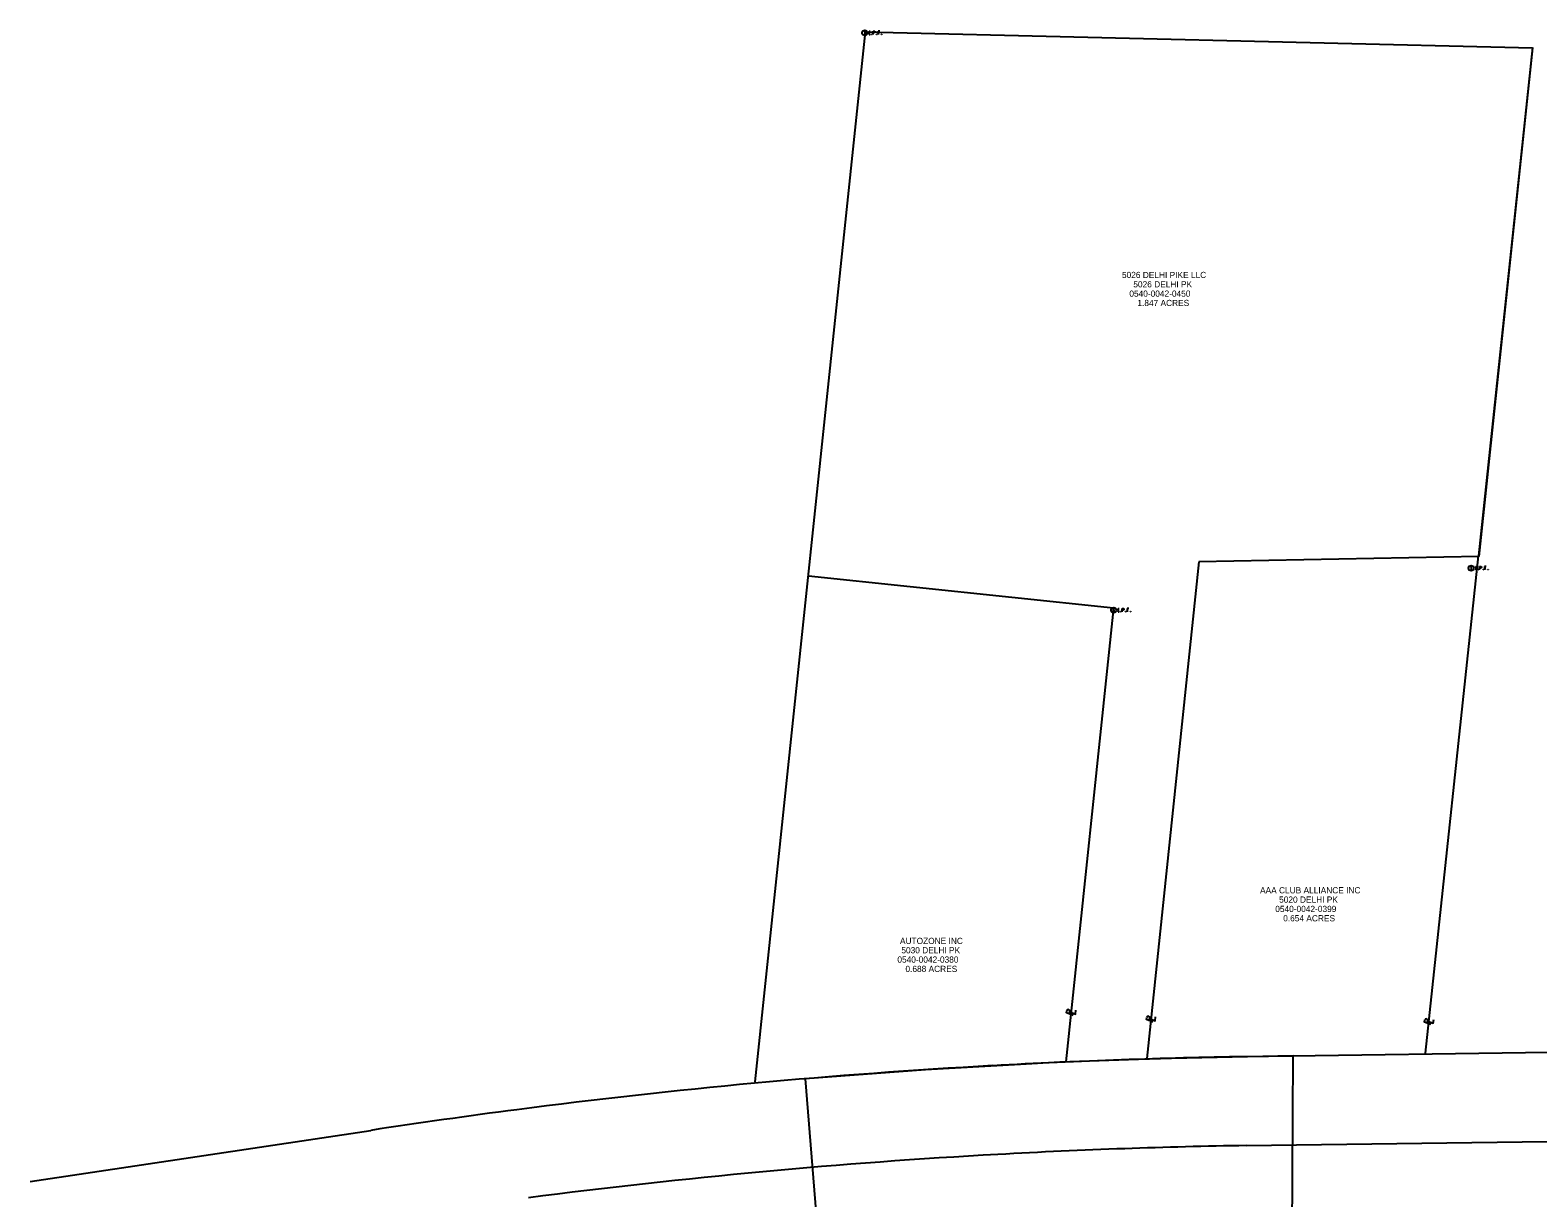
# Model space of a CAD drawing. Extents: x 1369159 to 1370720, y 404461 to 406422.
# Drawn here: x 1369242 to 1369920, y 405884 to 406409 of the extents above; entities that cross this region are included whole.
import ezdxf

# ---------------------------------------------------------------- set-up
doc = ezdxf.new("R2010")
doc.units = 0
for name, color, linetype in [('Default', 7, 'Continuous'), ('DR_P_Storm_Sewer', 7, 'Continuous'), ('DR_X_Cells', 7, 'Continuous'), ('GK_Drainage_Nodes', 7, 'Continuous'), ('SC_Scratch1', 7, 'Continuous'), ('XS_X_Pavt', 7, 'Continuous'), ('XS_X_Subgrade', 7, 'Continuous')]:
    doc.layers.add(name, color=color, linetype=linetype)

msp = doc.modelspace()

# ---------------------------------------------------------------- linework, layer by layer
at = {"layer": 'Default'}
for p, q in [((1369567.67, 405935.95), (1369617.23, 406408.28)), ((1369617.23, 406408.28), (1369917.15, 406401.09)), ((1369917.15, 406401.29), (1369892.87, 406172.49)), ((1369917.15, 406401.09), (1369893.14, 406172.25)), ((1369767.2, 406169.83), (1369743.75, 405946.36)), ((1369893.14, 406172.25), (1369767.2, 406169.83)), ((1369869.15, 405948.74), (1369892.87, 406172.49)), ((1369591.56, 406163.57), (1369728.83, 406149.16)), ((1369728.83, 406149.16), (1369707.39, 405944.83))]:
    msp.add_line(p, q, dxfattribs=at)
at = {"layer": 'DR_P_Storm_Sewer'}
for p, q in [((1369709.03, 405966.37), (1369709.16, 405967.66)), ((1369709.73, 405967.11), (1369709.73, 405967.11)), ((1369744.91, 405963.38), (1369745.05, 405964.67)), ((1369745.61, 405964.11), (1369745.61, 405964.11)), ((1369869.96, 405962.23), (1369870.09, 405963.52)), ((1369870.66, 405962.96), (1369870.66, 405962.96))]:
    msp.add_line(p, q, dxfattribs=at)
for points in [[(1369710.57, 405965.79), (1369707.7, 405966.88), (1369707.81, 405967.9)], [(1369708.8, 405967.47), (1369711.66, 405966.38), (1369711.84, 405968.11)], [(1369746.45, 405962.8), (1369743.58, 405963.88), (1369743.69, 405964.91)], [(1369744.69, 405964.48), (1369747.55, 405963.38), (1369747.73, 405965.12)], [(1369871.49, 405961.64), (1369868.63, 405962.73), (1369868.74, 405963.76)], [(1369869.73, 405963.32), (1369872.59, 405962.23), (1369872.77, 405963.96)]]:
    msp.add_lwpolyline(points, dxfattribs=at)
for centre, start, end in [((1369708.48, 405967.73), 354.48119, 165.3383), ((1369744.36, 405964.74), 354.48119, 165.3383), ((1369869.41, 405963.58), 354.41926, 165.27637)]:
    msp.add_arc(centre, 0.69, start, end, dxfattribs=at)
at = {"layer": 'DR_X_Cells'}
msp.add_lwpolyline([(1369642.22, 405861.02), (1369654.84, 405861.85), (1369684.92, 405863.95), (1369711.42, 405864.9), (1369728.97, 405865.6), (1369742.82, 405866.07), (1369752.88, 405866.4), (1369760.07, 405866.6), (1369765.46, 405866.74), (1369771.5, 405866.85), (1369782.46, 405867.11), (1369809.08, 405867.51), (1369809.6, 405947.53), (1369754.89, 405946.35), (1369739.98, 405945.96), (1369704.61, 405944.67), (1369686.9, 405943.7), (1369644.28, 405941.34), (1369590.13, 405937.27), (1369596.55, 405857.52), (1369610.3, 405858.65)], close=True, dxfattribs=at)
at = {"layer": 'SC_Scratch1'}
for p, q in [((1369616.89, 406407.96), (1369616.89, 406407.07)), ((1369618.92, 406408.64), (1369619.27, 406408.64)), ((1369618.92, 406407.04), (1369619.27, 406407.04)), ((1369619.1, 406407.04), (1369619.1, 406408.64)), ((1369619.99, 406407.18), (1369620.02, 406407.23)), ((1369619.99, 406407.12), (1369619.99, 406407.18)), ((1369620.02, 406407.07), (1369619.99, 406407.12)), ((1369620.02, 406407.23), (1369620.05, 406407.25)), ((1369620.05, 406407.04), (1369620.02, 406407.07)), ((1369620.05, 406407.25), (1369620.11, 406407.25)), ((1369620.11, 406407.04), (1369620.05, 406407.04)), ((1369620.11, 406407.25), (1369620.14, 406407.23)), ((1369620.14, 406407.07), (1369620.11, 406407.04)), ((1369620.14, 406407.23), (1369620.18, 406407.18)), ((1369620.18, 406407.12), (1369620.14, 406407.07)), ((1369620.18, 406407.18), (1369620.18, 406407.12)), ((1369620.66, 406407.04), (1369620.66, 406408.64)), ((1369620.66, 406408.64), (1369621.19, 406408.64)), ((1369621.19, 406407.86), (1369620.66, 406407.86)), ((1369621.19, 406408.64), (1369621.25, 406408.63)), ((1369621.28, 406407.87), (1369621.19, 406407.86)), ((1369621.25, 406408.63), (1369621.32, 406408.6)), ((1369621.33, 406407.9), (1369621.28, 406407.87)), ((1369621.32, 406408.6), (1369621.36, 406408.58)), ((1369621.37, 406407.92), (1369621.33, 406407.9)), ((1369621.36, 406408.58), (1369621.39, 406408.55)), ((1369621.41, 406407.96), (1369621.37, 406407.92)), ((1369621.39, 406408.55), (1369621.43, 406408.49)), ((1369621.45, 406408.05), (1369621.41, 406407.96)), ((1369621.43, 406408.49), (1369621.47, 406408.43)), ((1369621.48, 406408.12), (1369621.45, 406408.05)), ((1369621.47, 406408.43), (1369621.49, 406408.32)), ((1369621.49, 406408.17), (1369621.48, 406408.12)), ((1369621.49, 406408.32), (1369621.49, 406408.17)), ((1369622.24, 406407.18), (1369622.27, 406407.23)), ((1369622.24, 406407.12), (1369622.24, 406407.18)), ((1369622.27, 406407.07), (1369622.24, 406407.12)), ((1369622.27, 406407.23), (1369622.3, 406407.25)), ((1369622.3, 406407.04), (1369622.27, 406407.07)), ((1369622.3, 406407.25), (1369622.36, 406407.25)), ((1369622.36, 406407.04), (1369622.3, 406407.04)), ((1369622.36, 406407.25), (1369622.39, 406407.23)), ((1369622.39, 406407.07), (1369622.36, 406407.04)), ((1369622.39, 406407.23), (1369622.42, 406407.18)), ((1369622.42, 406407.12), (1369622.39, 406407.07)), ((1369622.42, 406407.18), (1369622.42, 406407.12)), ((1369623.67, 406408.64), (1369622.91, 406408.64)), ((1369622.91, 406408.64), (1369622.91, 406407.04)), ((1369622.91, 406407.86), (1369623.45, 406407.86)), ((1369624.39, 406407.18), (1369624.42, 406407.23)), ((1369624.39, 406407.12), (1369624.39, 406407.18)), ((1369624.42, 406407.07), (1369624.39, 406407.12)), ((1369624.42, 406407.23), (1369624.45, 406407.25)), ((1369624.45, 406407.04), (1369624.42, 406407.07)), ((1369624.45, 406407.25), (1369624.51, 406407.25)), ((1369624.51, 406407.04), (1369624.45, 406407.04)), ((1369624.51, 406407.25), (1369624.54, 406407.23)), ((1369624.54, 406407.07), (1369624.51, 406407.04)), ((1369624.54, 406407.23), (1369624.57, 406407.18)), ((1369624.57, 406407.12), (1369624.54, 406407.07)), ((1369624.57, 406407.18), (1369624.57, 406407.12)), ((1369889.62, 406167.12), (1369889.62, 406166.23)), ((1369891.65, 406167.8), (1369892, 406167.8)), ((1369891.65, 406166.2), (1369892, 406166.2)), ((1369891.83, 406166.2), (1369891.83, 406167.8)), ((1369892.72, 406166.34), (1369892.75, 406166.39)), ((1369892.72, 406166.28), (1369892.72, 406166.34)), ((1369892.75, 406166.23), (1369892.72, 406166.28)), ((1369892.75, 406166.39), (1369892.79, 406166.42)), ((1369892.79, 406166.2), (1369892.75, 406166.23)), ((1369892.79, 406166.42), (1369892.84, 406166.42)), ((1369892.84, 406166.2), (1369892.79, 406166.2)), ((1369892.84, 406166.42), (1369892.87, 406166.39)), ((1369892.87, 406166.23), (1369892.84, 406166.2)), ((1369892.87, 406166.39), (1369892.91, 406166.34)), ((1369892.91, 406166.28), (1369892.87, 406166.23)), ((1369892.91, 406166.34), (1369892.91, 406166.28)), ((1369893.39, 406166.2), (1369893.39, 406167.8)), ((1369893.39, 406167.8), (1369893.92, 406167.8)), ((1369893.92, 406167.02), (1369893.39, 406167.02)), ((1369893.92, 406167.8), (1369893.98, 406167.79)), ((1369894.01, 406167.03), (1369893.92, 406167.02)), ((1369893.98, 406167.79), (1369894.05, 406167.76)), ((1369894.06, 406167.06), (1369894.01, 406167.03)), ((1369894.05, 406167.76), (1369894.09, 406167.74)), ((1369894.1, 406167.08), (1369894.06, 406167.06)), ((1369894.09, 406167.74), (1369894.12, 406167.71)), ((1369894.14, 406167.12), (1369894.1, 406167.08)), ((1369894.12, 406167.71), (1369894.16, 406167.65)), ((1369894.19, 406167.21), (1369894.14, 406167.12)), ((1369894.16, 406167.65), (1369894.2, 406167.59)), ((1369894.21, 406167.28), (1369894.19, 406167.21)), ((1369894.2, 406167.59), (1369894.22, 406167.49)), ((1369894.22, 406167.33), (1369894.21, 406167.28)), ((1369894.22, 406167.49), (1369894.22, 406167.33)), ((1369894.97, 406166.34), (1369895, 406166.39)), ((1369894.97, 406166.28), (1369894.97, 406166.34)), ((1369895, 406166.23), (1369894.97, 406166.28)), ((1369895, 406166.39), (1369895.03, 406166.42)), ((1369895.03, 406166.2), (1369895, 406166.23)), ((1369895.03, 406166.42), (1369895.09, 406166.42)), ((1369895.09, 406166.2), (1369895.03, 406166.2)), ((1369895.09, 406166.42), (1369895.12, 406166.39)), ((1369895.12, 406166.23), (1369895.09, 406166.2)), ((1369895.12, 406166.39), (1369895.16, 406166.34)), ((1369895.16, 406166.28), (1369895.12, 406166.23)), ((1369895.16, 406166.34), (1369895.16, 406166.28)), ((1369896.4, 406167.8), (1369895.64, 406167.8)), ((1369895.64, 406167.8), (1369895.64, 406166.2)), ((1369895.64, 406167.02), (1369896.18, 406167.02)), ((1369897.12, 406166.34), (1369897.15, 406166.39)), ((1369897.12, 406166.28), (1369897.12, 406166.34)), ((1369897.15, 406166.23), (1369897.12, 406166.28)), ((1369897.15, 406166.39), (1369897.18, 406166.42)), ((1369897.18, 406166.2), (1369897.15, 406166.23)), ((1369897.18, 406166.42), (1369897.24, 406166.42)), ((1369897.24, 406166.2), (1369897.18, 406166.2)), ((1369897.24, 406166.42), (1369897.27, 406166.39)), ((1369897.27, 406166.23), (1369897.24, 406166.2)), ((1369897.27, 406166.39), (1369897.31, 406166.34)), ((1369897.31, 406166.28), (1369897.27, 406166.23)), ((1369897.31, 406166.34), (1369897.31, 406166.28)), ((1369730.9, 406148.89), (1369731.25, 406148.89)), ((1369731.07, 406147.29), (1369731.07, 406148.89)), ((1369732.64, 406147.29), (1369732.64, 406148.89)), ((1369732.64, 406148.89), (1369733.17, 406148.89)), ((1369733.17, 406148.89), (1369733.22, 406148.88)), ((1369733.22, 406148.88), (1369733.3, 406148.86)), ((1369733.3, 406148.86), (1369733.33, 406148.83)), ((1369733.33, 406148.83), (1369733.36, 406148.8)), ((1369733.36, 406148.8), (1369733.41, 406148.74)), ((1369733.41, 406148.74), (1369733.44, 406148.68)), ((1369733.44, 406148.68), (1369733.46, 406148.58)), ((1369733.46, 406148.58), (1369733.46, 406148.43)), ((1369735.65, 406148.89), (1369734.89, 406148.89)), ((1369734.89, 406148.89), (1369734.89, 406147.29)), ((1369728.86, 406148.21), (1369728.86, 406147.33)), ((1369730.9, 406147.29), (1369731.25, 406147.29)), ((1369731.96, 406147.43), (1369732, 406147.48)), ((1369731.96, 406147.37), (1369731.96, 406147.43)), ((1369732, 406147.32), (1369731.96, 406147.37)), ((1369732, 406147.48), (1369732.03, 406147.51)), ((1369732.03, 406147.29), (1369732, 406147.32)), ((1369732.03, 406147.51), (1369732.09, 406147.51)), ((1369732.09, 406147.29), (1369732.03, 406147.29)), ((1369732.09, 406147.51), (1369732.12, 406147.48)), ((1369732.12, 406147.32), (1369732.09, 406147.29)), ((1369732.12, 406147.48), (1369732.15, 406147.43)), ((1369732.15, 406147.37), (1369732.12, 406147.32)), ((1369732.15, 406147.43), (1369732.15, 406147.37)), ((1369733.17, 406148.11), (1369732.64, 406148.11)), ((1369733.25, 406148.12), (1369733.17, 406148.11)), ((1369733.31, 406148.15), (1369733.25, 406148.12)), ((1369733.34, 406148.17), (1369733.31, 406148.15)), ((1369733.39, 406148.21), (1369733.34, 406148.17)), ((1369733.43, 406148.3), (1369733.39, 406148.21)), ((1369733.45, 406148.38), (1369733.43, 406148.3)), ((1369733.46, 406148.43), (1369733.45, 406148.38)), ((1369734.21, 406147.43), (1369734.25, 406147.48)), ((1369734.21, 406147.37), (1369734.21, 406147.43)), ((1369734.25, 406147.32), (1369734.21, 406147.37)), ((1369734.25, 406147.48), (1369734.28, 406147.51)), ((1369734.28, 406147.29), (1369734.25, 406147.32)), ((1369734.28, 406147.51), (1369734.33, 406147.51)), ((1369734.33, 406147.29), (1369734.28, 406147.29)), ((1369734.33, 406147.51), (1369734.37, 406147.48)), ((1369734.37, 406147.32), (1369734.33, 406147.29)), ((1369734.37, 406147.48), (1369734.4, 406147.43)), ((1369734.4, 406147.37), (1369734.37, 406147.32)), ((1369734.4, 406147.43), (1369734.4, 406147.37)), ((1369734.89, 406148.11), (1369735.43, 406148.11)), ((1369736.36, 406147.43), (1369736.4, 406147.48)), ((1369736.36, 406147.37), (1369736.36, 406147.43)), ((1369736.4, 406147.32), (1369736.36, 406147.37)), ((1369736.4, 406147.48), (1369736.43, 406147.51)), ((1369736.43, 406147.29), (1369736.4, 406147.32)), ((1369736.43, 406147.51), (1369736.48, 406147.51)), ((1369736.48, 406147.29), (1369736.43, 406147.29)), ((1369736.48, 406147.51), (1369736.52, 406147.48)), ((1369736.52, 406147.32), (1369736.48, 406147.29)), ((1369736.52, 406147.48), (1369736.55, 406147.43)), ((1369736.55, 406147.37), (1369736.52, 406147.32)), ((1369736.55, 406147.43), (1369736.55, 406147.37))]:
    msp.add_line(p, q, dxfattribs=at)
for centre, radius in [((1369616.89, 406407.84), 1.2), ((1369616.89, 406408.49), 0.16), ((1369889.62, 406167), 1.2), ((1369889.62, 406167.65), 0.16), ((1369728.86, 406148.09), 1.2), ((1369728.86, 406148.74), 0.16)]:
    msp.add_circle(centre, radius, dxfattribs=at)
at = {"layer": 'XS_X_Pavt'}
msp.add_line((1369788.56, 405907.22), (1370023.59, 405910.4), dxfattribs=at)
for centre, radius, start, end in [((1369830.5, 403129.99), 2777.5, 91.99489, 93.17247), ((1369833, 403132.35), 2775.23, 90.9175, 92.04814), ((1369834.84, 403043.1), 2864.49, 93.16294, 97.40586)]:
    msp.add_arc(centre, radius, start, end, dxfattribs=at)
at = {"layer": 'XS_X_Subgrade'}
for p, q in [((1369787.95, 405947.22), (1369990.08, 405950.13)), ((1369241.57, 405891.12), (1369394.71, 405914.07))]:
    msp.add_line(p, q, dxfattribs=at)
for centre, radius, start, end in [((1369830.48, 403130.3), 2817.18, 91.99483, 93.1724), ((1369832.95, 403134.22), 2813.35, 90.91649, 92.04778), ((1369834.85, 403042.97), 2904.63, 93.16304, 97.40596), ((1369852.34, 402914.17), 3034.6, 97.41997, 98.67342)]:
    msp.add_arc(centre, radius, start, end, dxfattribs=at)

# ---------------------------------------------------------------- texts
at = {"layer": 'GK_Drainage_Nodes'}
for s, p in [('5026 DELHI PIKE LLC', (1369732.58, 406297.5)), ('0540-0042-0450', (1369735.9, 406289.1)), ('5026 DELHI PK', (1369737.69, 406293.3)), ('1.847 ACRES', (1369739.52, 406284.9)), ('AAA CLUB ALLIANCE INC', (1369794.68, 406020.68)), ('0540-0042-0399', (1369801.52, 406012.28)), ('5020 DELHI PK', (1369803.26, 406016.48)), ('0.654 ACRES', (1369805.09, 406008.08)), ('AUTOZONE INC', (1369632.75, 405997.9)), ('5030 DELHI PK', (1369633.37, 405993.7)), ('0540-0042-0380', (1369631.58, 405989.5)), ('0.688 ACRES', (1369635.2, 405985.3))]:
    msp.add_text(s, height=2.8, dxfattribs=at).set_placement(p)

doc.saveas('drawing.dxf')
